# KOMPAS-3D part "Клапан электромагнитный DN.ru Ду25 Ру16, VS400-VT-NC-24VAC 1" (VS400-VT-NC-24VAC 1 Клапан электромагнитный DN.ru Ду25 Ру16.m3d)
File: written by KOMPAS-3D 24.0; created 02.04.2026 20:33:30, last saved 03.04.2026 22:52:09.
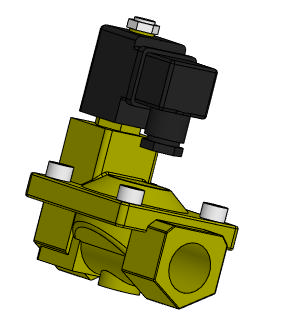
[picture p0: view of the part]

Document properties: Автор: artio; Полное имя файла: C:\Users\artio\OneDrive\Рабочий стол\Клапан электромагнитный DN.ru\VS400-VT-NC\VS400-VT-NC-24VAC 1 Клапан электромагнитный DN.ru Ду25 Ру16.m3d

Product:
- Body: Тело 1  | qty 1
    Масса: 1.76797
- Part/product: Клапан электромагнитный DN.ru Ду25 Ру16  | designation VS400-VT-NC-24VAC 1
    Масса: 1.524
    Раздел спецификации: Прочие изделия
    Примечание: D130-05499
    additional columns: ef56311e-7521-43dc-8291-0e6108b3d81d; VS400-ET-NC-220VAC 1; artio; c; Шероховатость не задана; Да

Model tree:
1. Операция без истории:1

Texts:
  VS400-VT-NC-24VAC 1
